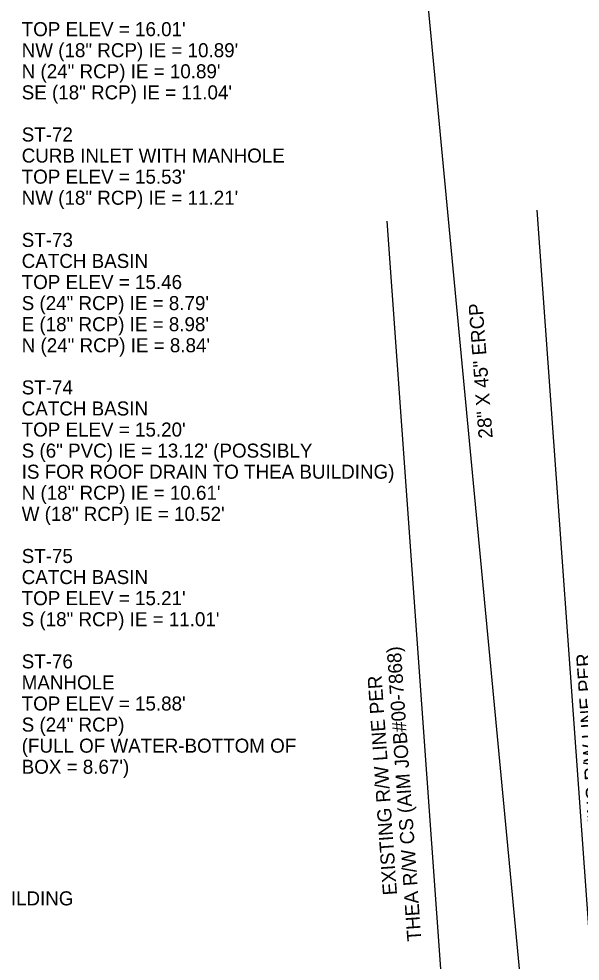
# Model space of a CAD drawing. Extents: x 509744 to 512285, y 1314862 to 1316822.
# Drawn here: x 511317.3 to 511429.2, y 1315714.8 to 1315902.6 of the extents above; entities that cross this region are included whole.
import ezdxf

# ---------------------------------------------------------------- set-up
doc = ezdxf.new("R2010")
doc.units = 0
for name, color, linetype in [('NonPlottingEle_dp', 7, 'Continuous'), ('PipeCulvert_ep', 7, 'Continuous'), ('RWLine_ep', 7, 'Continuous'), ('TextNotes', 7, 'Continuous'), ('TextTopoLabel_ep', 7, 'Continuous')]:
    doc.layers.add(name, color=color, linetype=linetype)

msp = doc.modelspace()

# ---------------------------------------------------------------- linework, layer by layer
at = {"layer": 'PipeCulvert_ep'}
msp.add_line((511420.86, 1315672.96), (511395.51, 1315941.43), dxfattribs=at)
at = {"layer": 'RWLine_ep'}
for p, q in [((511420.57, 1315864.4), (511435.34, 1315658.84)), ((511390.65, 1315862.25), (511405.24, 1315659.09))]:
    msp.add_line(p, q, dxfattribs=at)

# ---------------------------------------------------------------- texts
at = {"layer": 'NonPlottingEle_dp'}
for s, p in [("TOP ELEV = 16.01'", (511317.9, 1315899.1)), ('NW (18" RCP) IE = 10.89\'', (511317.9, 1315894.9)), ('N (24" RCP) IE = 10.89\'', (511317.9, 1315890.7)), ('SE (18" RCP) IE = 11.04\'', (511317.9, 1315886.5)), ('ST-72', (511317.9, 1315878.1)), ('CURB INLET WITH MANHOLE', (511317.9, 1315873.9)), ("TOP ELEV = 15.53'", (511317.9, 1315869.7)), ('NW (18" RCP) IE = 11.21\'', (511317.9, 1315865.5)), ('ST-73', (511317.9, 1315857.1)), ('CATCH BASIN', (511317.9, 1315852.9)), ('TOP ELEV = 15.46', (511317.9, 1315848.7)), ('S (24" RCP) IE = 8.79\'', (511317.9, 1315844.5)), ('E (18" RCP) IE = 8.98\'', (511317.9, 1315840.3)), ('N (24" RCP) IE = 8.84\'', (511317.9, 1315836.1)), ('ST-74', (511317.9, 1315827.7)), ('CATCH BASIN', (511317.9, 1315823.5)), ("TOP ELEV = 15.20'", (511317.9, 1315819.3)), ('S (6" PVC) IE = 13.12\' (POSSIBLY', (511317.9, 1315815.1)), ('IS FOR ROOF DRAIN TO THEA BUILDING)', (511317.9, 1315810.9)), ('N (18" RCP) IE = 10.61\'', (511317.9, 1315806.7)), ('W (18" RCP) IE = 10.52\'', (511317.9, 1315802.5)), ('ST-75', (511317.9, 1315794.1)), ('CATCH BASIN', (511317.9, 1315789.9)), ("TOP ELEV = 15.21'", (511317.9, 1315785.7)), ('S (18" RCP) IE = 11.01\'', (511317.9, 1315781.5)), ('ST-76', (511317.9, 1315773.1)), ('MANHOLE', (511317.9, 1315768.9)), ("TOP ELEV = 15.88'", (511317.9, 1315764.7)), ('S (24" RCP)', (511317.9, 1315760.5)), ('(FULL OF WATER-BOTTOM OF', (511317.9, 1315756.3)), ("BOX = 8.67')", (511317.9, 1315752.1))]:
    msp.add_text(s, height=2.8, dxfattribs=at).set_placement(p)
msp.add_text('28" X 45" ERCP', height=2.8, rotation=94.3295, dxfattribs=at).set_placement((511411.75, 1315819.04))
at = {"layer": 'TextNotes'}
for s, p in [('THEA R/W CS (AIM JOB#00-7868)', (511397.54, 1315718.83)), ('EXISTING R/W LINE PER', (511434.23, 1315732.41)), ('EXISTING R/W LINE PER', (511392.69, 1315727.99))]:
    msp.add_text(s, height=2.8, rotation=94.0425, dxfattribs=at).set_placement(p)
at = {"layer": 'TextTopoLabel_ep'}
msp.add_text('MASONARY BUILDING', height=2.8, dxfattribs=at).set_placement((511288.06, 1315725.87))

doc.saveas('drawing.dxf')
